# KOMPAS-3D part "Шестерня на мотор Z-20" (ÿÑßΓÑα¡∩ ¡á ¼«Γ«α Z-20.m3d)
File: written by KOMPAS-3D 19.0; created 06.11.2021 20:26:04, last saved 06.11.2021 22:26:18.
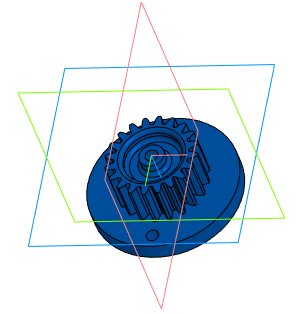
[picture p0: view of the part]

Document properties: Полное имя файла: D:\3D_print\3D проекты Компас 3D\Редуктор (Снова)\Шестерня на мотор Z-20.m3d

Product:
- Part/product: Шестерня на мотор Z-20
    Материал: АБС 0603Т ТУ 2214-019-002 03521-96 (density 0 kg/m3)

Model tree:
1. ЛСК (Шестерня цилиндрическая с внешними зубьями):1  (with: Шестерня цилиндрическая с внешними зубьями:1, Плоскость XY, Плоскость ZX, Плоскость ZY, Ось X, Ось Y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)  (labels: &Фаска (Шестерня цилиндрическая с внешними зубьями):1)
     Ось X. Z = -1; Ось Y. X = -1; Ось Z. Y = 1; Угол 1 = 360
2. Эскиз для винтовой линии (Шестерня цилиндрическая с внешними зубьями):1  (with: Винтовая линия (Шестерня цилиндрическая с внешними зубьями):1, Шестерня цилиндрическая с внешними зубьями:1, Впадина прямая (Шестерня цилиндрическая с внешними зубьями):1, Впадина косая (Шестерня цилиндрическая с внешними зубьями):1, Массив впадин (Шестерня цилиндрическая с внешними зубьями):1)  (2 pattern instances)
     Число витков = 0.00835455; Смещение 2 = 6
3. Впадина прямая (Шестерня цилиндрическая с внешними зубьями):1  (with: Массив впадин (Шестерня цилиндрическая с внешними зубьями):1, Шестерня цилиндрическая с внешними зубьями:1)  (20 pattern instances)
     N 1 = 1; Шаг 1 = 1; Номер 1 = 1
4. Впадина косая (Шестерня цилиндрическая с внешними зубьями):1  (with: Винтовая линия (Шестерня цилиндрическая с внешними зубьями):1)
     N 1 = 1; Шаг 1 = 1; Номер 1 = 1
5. Шестерня цилиндрическая с внешними зубьями:1
6. Эскиз:5  (with: Цилиндр (Шестерня цилиндрическая с внешними зубьями):1, Впадина прямая (Шестерня цилиндрическая с внешними зубьями):1)
7. Элемент выдавливания:3
     Расстояние 2 = 6
8. Эскиз:6  (with: Цилиндр (Шестерня цилиндрическая с внешними зубьями):1, Элемент выдавливания:3)
9. Элемент выдавливания:4  (with: Цилиндр (Шестерня цилиндрическая с внешними зубьями):1)
     Расстояние 2 = 3; Смещение 2 = 3
10. Скругление:1  (with: Элемент выдавливания:4)
     Радиус = 1
11. Элемент выдавливания:5  (with: Цилиндр (Шестерня цилиндрическая с внешними зубьями):1, Элемент выдавливания:8)  (labels: Шестерня на мотор Z-20)
     Расстояние 1 = 4.43522; Смещение 1 = 0.6
12. Эскиз:7  (with: Элемент выдавливания:5, Элемент выдавливания:9)  (labels: Шестерня на мотор Z-20)
13. Элемент выдавливания:6  (with: Элемент выдавливания:8)  (labels: Шестерня на мотор Z-20; АБС 0603Т ТУ 2214-019-002 03521-96)
     Расстояние 1 = 4.2; Смещение 1 = 1

Expressions: (VGExtS_1_z*VGExtS_1_M)/COSD(VGExtS_1_Beta); 360/VGExtS_1_z
Referenced files in D:\3D_print\3D проекты Компас 3D\Редуктор (Снова)\: Намоточный станок (Projects 6).a3d
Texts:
  SHAFT3D
  Количество отображаемых зубьев
  Угол наклона линии зубьев
  Шаг по кольцевому направлению
  (VGExtS_1_Beta>0)?(M_PI*VGExtS_1_z*VGExtS_1_M/SIND(VGExtS_1_Beta)):1000
  (VGExtS_1_Da<=0||VGExtS_1_Da>5e+7)?25:VGExtS_1_Da
  (VGExtS_1_H<=0||VGExtS_1_H>5e+7)?25:VGExtS_1_H
  VGExtS_1_zz<VGExtS_1_z?(VGExtS_1_zz+1):VGExtS_1_z
  (VGExtS_1_zz<=0||VGExtS_1==1)||(VGExtS_1_Beta>0)?1:0
  (VGExtS_1_zz<=0||VGExtS_1==1)||(VGExtS_1_Beta<=0)?1:0
  (VGExtS_1==1)||(VGExtS_1_Beta<=0)?1:0
  Щелевой оптический датчик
